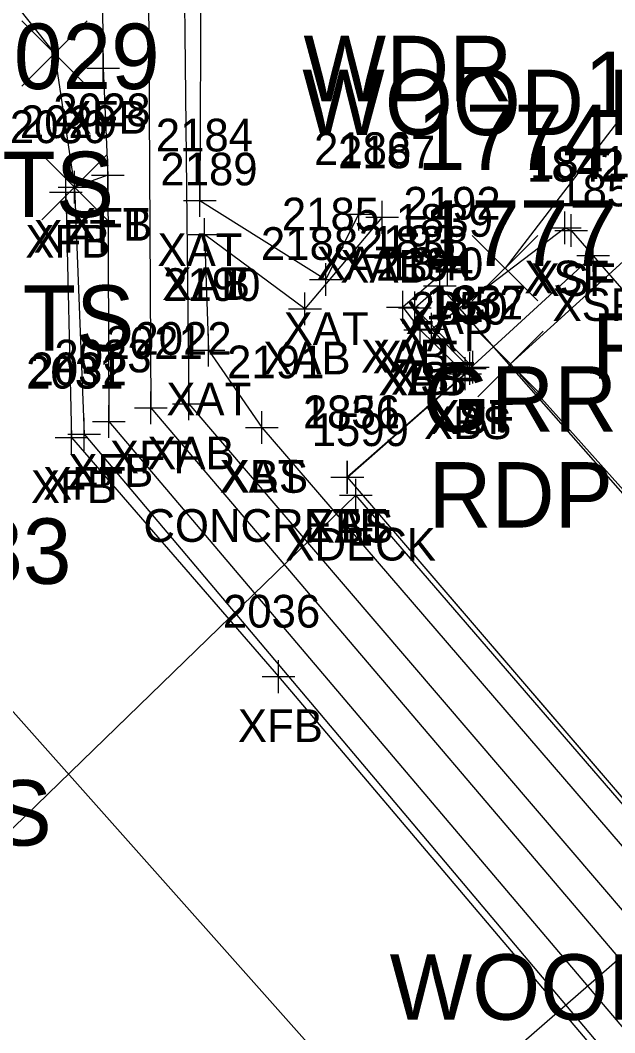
# Model space of a CAD drawing. Extents: x 1647133 to 1649138, y 411736 to 414924.
# Drawn here: x 1648964.63 to 1648982.81, y 412208.47 to 412239.42 of the extents above; entities that cross this region are included whole.
import ezdxf

# ---------------------------------------------------------------- set-up
doc = ezdxf.new("R2010")
doc.units = 0
for name, color, linetype in [('B_A', 7, 'Continuous'), ('B_C', 7, 'Continuous'), ('B_I', 7, 'Continuous'), ('B_TIC', 7, 'Continuous'), ('BDEFAULT', 7, 'Continuous'), ('BELB', 7, 'Continuous'), ('BFT', 7, 'Continuous'), ('BSE', 7, 'Continuous'), ('BSUBM', 7, 'Continuous'), ('L_A', 7, 'Continuous'), ('L_I', 7, 'Continuous'), ('L_TIC', 7, 'Continuous'), ('LELB', 7, 'Continuous'), ('P_A', 7, 'Continuous'), ('P_I', 7, 'Continuous'), ('P_TIC', 7, 'Continuous'), ('PET', 7, 'Continuous'), ('R_A', 7, 'Continuous'), ('R_C', 7, 'Continuous'), ('R_I', 7, 'Continuous'), ('R_TIC', 7, 'Continuous'), ('RGR', 7, 'Continuous')]:
    doc.layers.add(name, color=color, linetype=linetype)

msp = doc.modelspace()

# ---------------------------------------------------------------- linework, layer by layer
at = {"layer": 'B_TIC'}
for p, q in [((1648967.163, 412237.956), (1648967.239, 412237.956)), ((1648967.31, 412234.686), (1648967.386, 412234.686)), ((1648967.31, 412234.686), (1648967.386, 412234.686)), ((1648966.026, 412234.167), (1648966.101, 412234.167)), ((1648966.294, 412234.321), (1648966.37, 412234.321)), ((1648970.123, 412233.914), (1648970.198, 412233.914)), ((1648974.992, 412233.498), (1648975.067, 412233.498)), ((1648975.698, 412233.4), (1648975.773, 412233.4)), ((1648981.286, 412233.076), (1648981.362, 412233.076)), ((1648981.482, 412232.993), (1648981.558, 412232.993)), ((1648970.266, 412232.876), (1648970.342, 412232.876)), ((1648970.266, 412232.876), (1648970.342, 412232.876)), ((1648982.151, 412232.234), (1648982.227, 412232.234)), ((1648977.698, 412231.83), (1648977.774, 412231.83)), ((1648973.98, 412231.5), (1648974.056, 412231.5)), ((1648977.467, 412231.306), (1648977.543, 412231.306)), ((1648977.467, 412231.306), (1648977.543, 412231.306)), ((1648973.34, 412230.598), (1648973.416, 412230.598)), ((1648976.333, 412230.656), (1648976.409, 412230.656)), ((1648976.705, 412230.631), (1648976.78, 412230.631)), ((1648976.865, 412229.959), (1648976.94, 412229.959)), ((1648976.865, 412229.959), (1648976.94, 412229.959)), ((1648977.208, 412229.977), (1648977.283, 412229.977)), ((1648977.208, 412229.977), (1648977.283, 412229.977)), ((1648970.393, 412229.343), (1648970.468, 412229.343)), ((1648978.239, 412228.62), (1648978.315, 412228.62)), ((1648978.383, 412228.778), (1648978.459, 412228.778)), ((1648978.383, 412228.778), (1648978.459, 412228.778)), ((1648978.477, 412228.815), (1648978.552, 412228.815)), ((1648969.792, 412227.697), (1648969.867, 412227.697)), ((1648968.625, 412227.573), (1648968.701, 412227.573)), ((1648967.343, 412227.16), (1648967.418, 412227.16)), ((1648966.583, 412226.766), (1648966.658, 412226.766)), ((1648972.019, 412226.979), (1648972.095, 412226.979)), ((1648972.019, 412226.979), (1648972.095, 412226.979)), ((1648966.197, 412226.664), (1648966.272, 412226.664)), ((1648974.627, 412225.452), (1648974.702, 412225.452)), ((1648974.643, 412225.453), (1648974.719, 412225.453)), ((1648974.895, 412224.907), (1648974.971, 412224.907)), ((1648974.895, 412224.907), (1648974.971, 412224.907)), ((1648972.528, 412219.358), (1648972.603, 412219.358))]:
    msp.add_line(p, q, dxfattribs=at)
for points in [[(1648967.16, 412237.456), (1648967.16, 412238.456)], [(1648966.66, 412237.956), (1648967.66, 412237.956)], [(1648967.307, 412234.186), (1648967.307, 412235.186)], [(1648967.307, 412234.186), (1648967.307, 412235.186)], [(1648966.291, 412233.821), (1648966.291, 412234.821)], [(1648966.022, 412233.667), (1648966.022, 412234.667)], [(1648966.807, 412234.686), (1648967.807, 412234.686)], [(1648966.807, 412234.686), (1648967.807, 412234.686)], [(1648965.522, 412234.167), (1648966.522, 412234.167)], [(1648965.791, 412234.321), (1648966.791, 412234.321)], [(1648970.119, 412233.414), (1648970.119, 412234.414)], [(1648969.619, 412233.914), (1648970.619, 412233.914)], [(1648974.988, 412232.998), (1648974.988, 412233.998)], [(1648975.694, 412232.9), (1648975.694, 412233.9)], [(1648974.488, 412233.498), (1648975.488, 412233.498)], [(1648981.283, 412232.576), (1648981.283, 412233.576)], [(1648970.263, 412232.376), (1648970.263, 412233.376)], [(1648970.263, 412232.376), (1648970.263, 412233.376)], [(1648975.194, 412233.4), (1648976.194, 412233.4)], [(1648981.479, 412232.493), (1648981.479, 412233.493)], [(1648980.783, 412233.076), (1648981.783, 412233.076)], [(1648980.979, 412232.993), (1648981.979, 412232.993)], [(1648969.763, 412232.876), (1648970.763, 412232.876)], [(1648969.763, 412232.876), (1648970.763, 412232.876)], [(1648982.148, 412231.734), (1648982.148, 412232.734)], [(1648977.695, 412231.33), (1648977.695, 412232.33)], [(1648973.977, 412231), (1648973.977, 412232)], [(1648981.648, 412232.234), (1648982.648, 412232.234)], [(1648977.195, 412231.83), (1648978.195, 412231.83)], [(1648977.464, 412230.806), (1648977.464, 412231.806)], [(1648977.464, 412230.806), (1648977.464, 412231.806)], [(1648973.477, 412231.5), (1648974.477, 412231.5)], [(1648973.337, 412230.098), (1648973.337, 412231.098)], [(1648976.33, 412230.156), (1648976.33, 412231.156)], [(1648976.701, 412230.131), (1648976.701, 412231.131)], [(1648976.964, 412231.306), (1648977.964, 412231.306)], [(1648976.964, 412231.306), (1648977.964, 412231.306)], [(1648972.837, 412230.598), (1648973.837, 412230.598)], [(1648975.83, 412230.656), (1648976.83, 412230.656)], [(1648976.201, 412230.631), (1648977.201, 412230.631)], [(1648976.861, 412229.459), (1648976.861, 412230.459)], [(1648976.861, 412229.459), (1648976.861, 412230.459)], [(1648977.204, 412229.477), (1648977.204, 412230.477)], [(1648977.204, 412229.477), (1648977.204, 412230.477)], [(1648970.389, 412228.843), (1648970.389, 412229.843)], [(1648976.361, 412229.959), (1648977.361, 412229.959)], [(1648976.361, 412229.959), (1648977.361, 412229.959)], [(1648976.704, 412229.977), (1648977.704, 412229.977)], [(1648976.704, 412229.977), (1648977.704, 412229.977)], [(1648969.889, 412229.343), (1648970.889, 412229.343)], [(1648978.38, 412228.278), (1648978.38, 412229.278)], [(1648978.38, 412228.278), (1648978.38, 412229.278)], [(1648978.473, 412228.315), (1648978.473, 412229.315)], [(1648978.236, 412228.12), (1648978.236, 412229.12)], [(1648977.736, 412228.62), (1648978.736, 412228.62)], [(1648977.88, 412228.778), (1648978.88, 412228.778)], [(1648977.88, 412228.778), (1648978.88, 412228.778)], [(1648977.973, 412228.815), (1648978.973, 412228.815)], [(1648968.622, 412227.073), (1648968.622, 412228.073)], [(1648969.788, 412227.197), (1648969.788, 412228.197)], [(1648967.339, 412226.66), (1648967.339, 412227.66)], [(1648969.288, 412227.697), (1648970.288, 412227.697)], [(1648968.122, 412227.573), (1648969.122, 412227.573)], [(1648972.016, 412226.479), (1648972.016, 412227.479)], [(1648972.016, 412226.479), (1648972.016, 412227.479)], [(1648966.193, 412226.164), (1648966.193, 412227.164)], [(1648966.579, 412226.266), (1648966.579, 412227.266)], [(1648966.839, 412227.16), (1648967.839, 412227.16)], [(1648966.079, 412226.766), (1648967.079, 412226.766)], [(1648971.516, 412226.979), (1648972.516, 412226.979)], [(1648971.516, 412226.979), (1648972.516, 412226.979)], [(1648965.693, 412226.664), (1648966.693, 412226.664)], [(1648974.623, 412224.952), (1648974.623, 412225.952)], [(1648974.64, 412224.953), (1648974.64, 412225.953)], [(1648974.123, 412225.452), (1648975.123, 412225.452)], [(1648974.14, 412225.453), (1648975.14, 412225.453)], [(1648974.892, 412224.407), (1648974.892, 412225.407)], [(1648974.892, 412224.407), (1648974.892, 412225.407)], [(1648974.392, 412224.907), (1648975.392, 412224.907)], [(1648974.392, 412224.907), (1648975.392, 412224.907)], [(1648972.524, 412218.858), (1648972.524, 412219.858)], [(1648972.024, 412219.358), (1648973.024, 412219.358)]]:
    msp.add_lwpolyline(points, dxfattribs=at)
at = {"layer": 'BDEFAULT'}
for points in [[(1648977.204, 412229.977), (1648981.283, 412233.076), (1648981.479, 412232.993), (1648988.032, 412225.443), (1648994.682, 412218.108), (1648994.599, 412217.943), (1648990.827, 412214.803), (1648989.969, 412215.704), (1648993.909, 412218.83), (1648992.104, 412220.957), (1648984.174, 412229.914), (1648982.148, 412232.234), (1648978.38, 412228.778)], [(1648977.204, 412229.977), (1648978.38, 412228.778)]]:
    msp.add_lwpolyline(points, dxfattribs=at)
at = {"layer": 'BELB'}
for points in [[(1648856.366, 412097.638), (1648845.782, 412109.602), (1648891.837, 412149.616), (1648923.124, 412177.419), (1648960.58, 412211.026), (1648974.892, 412224.907)], [(1648856.366, 412097.638), (1648904.081, 412141.155), (1648932.964, 412166.557), (1648970.055, 412199.522), (1648985.33, 412212.818), (1648974.892, 412224.907)]]:
    msp.add_lwpolyline(points, dxfattribs=at)
at = {"layer": 'BFT'}
for points in [[(1648969.053, 412251.503), (1648967.008, 412251.583), (1648967.16, 412237.956), (1648967.307, 412234.686), (1648967.339, 412227.16), (1648986.205, 412204.915), (1649003.564, 412196.539), (1649004.665, 412197.942)], [(1648969.525, 412251.264), (1648968.489, 412251.237), (1648968.622, 412227.573), (1648987.025, 412205.95), (1649003.857, 412197.685), (1649004.163, 412198.216)], [(1648967.307, 412234.686), (1648966.291, 412234.321), (1648966.579, 412226.766), (1648985.698, 412204.116), (1649004.144, 412195.12), (1649003.564, 412196.539)], [(1648966.022, 412234.167), (1648966.193, 412226.664), (1648972.524, 412219.358), (1648985.521, 412204.036), (1649004.013, 412194.899)]]:
    msp.add_lwpolyline(points, dxfattribs=at)
at = {"layer": 'BSE'}
for points in [[(1648976.861, 412229.959), (1648978.236, 412228.62), (1648974.623, 412225.452), (1648985.971, 412212.236), (1648989.592, 412215.456)], [(1648972.016, 412226.979), (1648987.261, 412209.275)]]:
    msp.add_lwpolyline(points, dxfattribs=at)
at = {"layer": 'BSUBM'}
for points in [[(1648980.212, 412272.224), (1648969.681, 412271.317), (1648969.261, 412266.421), (1648968.934, 412254.381), (1648969.053, 412251.503), (1648969.525, 412251.264), (1648969.788, 412227.697), (1648987.092, 412207.478), (1648990.118, 412205.514), (1649004.163, 412198.216), (1649004.665, 412197.942), (1649016.348, 412193.098), (1649025.312, 412183.014), (1649046.031, 412166.296)], [(1648981.041, 412271.638), (1648970.113, 412271.021), (1648970.035, 412266.898), (1648970.226, 412258.175), (1648970.119, 412233.914), (1648973.977, 412231.5), (1648974.988, 412233.498)], [(1648975.694, 412233.4), (1648973.337, 412230.598), (1648970.263, 412232.876)], [(1648970.263, 412232.876), (1648970.389, 412229.343), (1648972.016, 412226.979)], [(1648977.695, 412231.83), (1648976.33, 412230.656), (1648976.861, 412229.959)], [(1648999.219, 412221.632), (1648999.802, 412220.975), (1648991.493, 412214.206), (1648989.898, 412215.859), (1648985.917, 412212.32), (1648974.64, 412225.453), (1648978.473, 412228.815), (1648976.701, 412230.631), (1648977.464, 412231.306)], [(1648999.219, 412221.632), (1648991.48, 412215.41), (1648977.464, 412231.306)]]:
    msp.add_lwpolyline(points, dxfattribs=at)
at = {"layer": 'L_TIC'}
for points in [[(1648964.672, 412237.406), (1648966.672, 412239.406)], [(1648966.672, 412237.406), (1648964.672, 412239.406)], [(1648965.291, 412233.321), (1648967.291, 412235.321)], [(1648967.291, 412233.321), (1648965.291, 412235.321)]]:
    msp.add_lwpolyline(points, dxfattribs=at)
at = {"layer": 'LELB'}
for points in [[(1648921.867, 412322.911), (1648930.857, 412302.743), (1648938.048, 412285.866), (1648946.876, 412268.508), (1648959.298, 412246.43), (1648965.672, 412238.406), (1648966.291, 412234.321)], [(1648910.338, 412307.481), (1648923.401, 412285.734), (1648930.01, 412277.072), (1648939.665, 412266.792), (1648945.948, 412259.157), (1648943.1, 412258.499), (1648935.158, 412254.464), (1648928.495, 412254.282), (1648924.406, 412254.203), (1648925.497, 412246.049), (1648929.643, 412242.699), (1648937.314, 412237.257), (1648939.737, 412232.884), (1648942.092, 412231.581), (1648961.498, 412231.409), (1648963.583, 412219.195), (1648985.506, 412194.573), (1648993.764, 412177.977), (1649005.161, 412156.054), (1649014.951, 412138.525), (1649020.659, 412120.018), (1649027.353, 412106.948), (1649037.638, 412094.49)]]:
    msp.add_lwpolyline(points, dxfattribs=at)
at = {"layer": 'P_TIC'}
for points in [[(1648978.622, 412227.916), (1648980.622, 412229.916)], [(1648980.622, 412227.916), (1648978.622, 412229.916)]]:
    msp.add_lwpolyline(points, dxfattribs=at)
at = {"layer": 'PET'}
msp.add_lwpolyline([(1648998.767, 412333.423), (1648994.313, 412324.566), (1648993.834, 412315.066), (1649000.687, 412300.559), (1649003.42, 412288.198), (1649004.904, 412270.19), (1649001.609, 412254.477), (1648993.905, 412243.995), (1648984.626, 412233.464), (1648979.622, 412228.916), (1648985.327, 412222.555), (1648990.487, 412216.934), (1649002.33, 412227.191), (1649016.429, 412237.436), (1649036.674, 412252.918), (1649058.783, 412267.778), (1649074.295, 412277.904), (1649090.06, 412287.47)], dxfattribs=at)
at = {"layer": 'R_TIC'}
for points in [[(1648978.455, 412230.845), (1648980.455, 412232.845)], [(1648980.455, 412230.845), (1648978.455, 412232.845)]]:
    msp.add_lwpolyline(points, dxfattribs=at)
at = {"layer": 'RGR'}
msp.add_lwpolyline([(1648989.49, 412244.914), (1648979.455, 412231.845)], dxfattribs=at)

# ---------------------------------------------------------------- texts
at = {"layer": 'B_A'}
for s, p in [('XFB', (1648965.919, 412235.956)), ('XFT', (1648966.051, 412232.686)), ('XFB', (1648966.067, 412232.686)), ('XFT', (1648965.035, 412232.321)), ('XFB', (1648964.782, 412232.167)), ('XAT', (1648968.824, 412231.914)), ('XAT', (1648973.693, 412231.498)), ('XAB', (1648974.415, 412231.4)), ('XSF', (1648980.043, 412231.076)), ('XSF', (1648980.239, 412230.993)), ('XAT', (1648968.968, 412230.876)), ('XAB', (1648968.983, 412230.876)), ('XSF', (1648980.908, 412230.234)), ('XAB', (1648976.415, 412229.83)), ('XAT', (1648972.682, 412229.5)), ('XAT', (1648976.169, 412229.306)), ('XAT', (1648976.169, 412229.306)), ('XAB', (1648972.057, 412228.598)), ('XAB', (1648975.05, 412228.656)), ('XAT', (1648975.406, 412228.631)), ('XAB', (1648975.582, 412227.959)), ('XBS', (1648975.602, 412227.959)), ('XSF', (1648975.964, 412227.977)), ('XSF', (1648975.964, 412227.977)), ('XAT', (1648969.094, 412227.343)), ('XBS', (1648976.976, 412226.62)), ('XSF', (1648977.14, 412226.778)), ('XSF', (1648977.14, 412226.778)), ('XAT', (1648977.178, 412226.815)), ('XAB', (1648968.509, 412225.697)), ('XFT', (1648967.366, 412225.573)), ('XFB', (1648966.099, 412225.16)), ('XFT', (1648965.323, 412224.766)), ('XAT', (1648970.721, 412224.979)), ('XBS', (1648970.756, 412224.979)), ('XFB', (1648964.953, 412224.664)), ('XAT', (1648973.345, 412223.453)), ('XBS', (1648973.363, 412223.452)), ('XDECK', (1648972.734, 412222.907)), ('XDECK', (1648972.734, 412222.907)), ('XFB', (1648971.284, 412217.358))]:
    msp.add_text(s, height=1, dxfattribs=at).set_placement(p)
at = {"layer": 'B_C'}
msp.add_text('CONCRETE', height=1, dxfattribs=at).set_placement((1648968.394, 412223.479))
at = {"layer": 'B_I'}
for s, p in [('2028', (1648965.638, 412236.186)), ('2028', (1648965.638, 412236.186)), ('2030', (1648964.309, 412235.667)), ('2029', (1648964.618, 412235.821)), ('2184', (1648968.773, 412235.414)), ('2186', (1648973.614, 412234.998)), ('2187', (1648974.348, 412234.9)), ('2189', (1648968.913, 412234.376)), ('2189', (1648968.913, 412234.376)), ('1842', (1648980.132, 412234.493)), ('1841', (1648980.22, 412234.576)), ('1851', (1648981.085, 412233.734)), ('2192', (1648976.348, 412233.33)), ('2185', (1648972.63, 412233)), ('1839', (1648976.113, 412232.806)), ('1839', (1648976.113, 412232.806)), ('2188', (1648971.99, 412232.098)), ('2193', (1648974.983, 412232.156)), ('1838', (1648975.355, 412232.131)), ('2194', (1648975.515, 412231.459)), ('2194', (1648975.515, 412231.459)), ('1840', (1648975.815, 412231.477)), ('1840', (1648975.815, 412231.477)), ('2190', (1648968.999, 412230.843)), ('1837', (1648977.127, 412230.315)), ('2350', (1648976.562, 412230.12)), ('1852', (1648977.033, 412230.278)), ('1852', (1648977.033, 412230.278)), ('2022', (1648968.119, 412229.197)), ('2021', (1648967.236, 412229.073)), ('2033', (1648965.67, 412228.66)), ('2191', (1648970.953, 412228.479)), ('2191', (1648970.953, 412228.479)), ('2031', (1648964.807, 412228.164)), ('2032', (1648964.91, 412228.266)), ('2351', (1648973.277, 412226.952)), ('1836', (1648973.266, 412226.953)), ('1599', (1648973.541, 412226.407)), ('1599', (1648973.541, 412226.407)), ('2036', (1648970.828, 412220.858))]:
    msp.add_text(s, height=1, dxfattribs=at).set_placement(p)
at = {"layer": 'L_A'}
for s, p in [('WDR', (1648973.291, 412236.95)), ('TS', (1648964.081, 412233.406)), ('TS', (1648964.7, 412229.321)), ('BS', (1648962.024, 412214.195))]:
    msp.add_text(s, height=2, dxfattribs=at).set_placement(p)
at = {"layer": 'L_I'}
for s, p in [('2029', (1648962.944, 412237.321)), ('2083', (1648960.244, 412222.195))]:
    msp.add_text(s, height=2, dxfattribs=at).set_placement(p)
at = {"layer": 'P_A'}
for p in [(1648982.114, 412228.464), (1648977.11, 412223.916)]:
    msp.add_text('RDP', height=2, dxfattribs=at).set_placement(p)
at = {"layer": 'P_I'}
for s, p in [('1776', (1648981.878, 412236.464)), ('1777', (1648976.929, 412231.916))]:
    msp.add_text(s, height=2, dxfattribs=at).set_placement(p)
at = {"layer": 'R_A'}
msp.add_text('GRR', height=2, dxfattribs=at).set_placement((1648976.943, 412226.845))
at = {"layer": 'R_C'}
for p in [(1648973.254, 412235.914), (1648975.926, 412208.871)]:
    msp.add_text('WOOD POST & PLANK', height=2, dxfattribs=at).set_placement(p)
at = {"layer": 'R_I'}
msp.add_text('1774', height=2, dxfattribs=at).set_placement((1648976.762, 412234.845))

doc.saveas('drawing.dxf')
